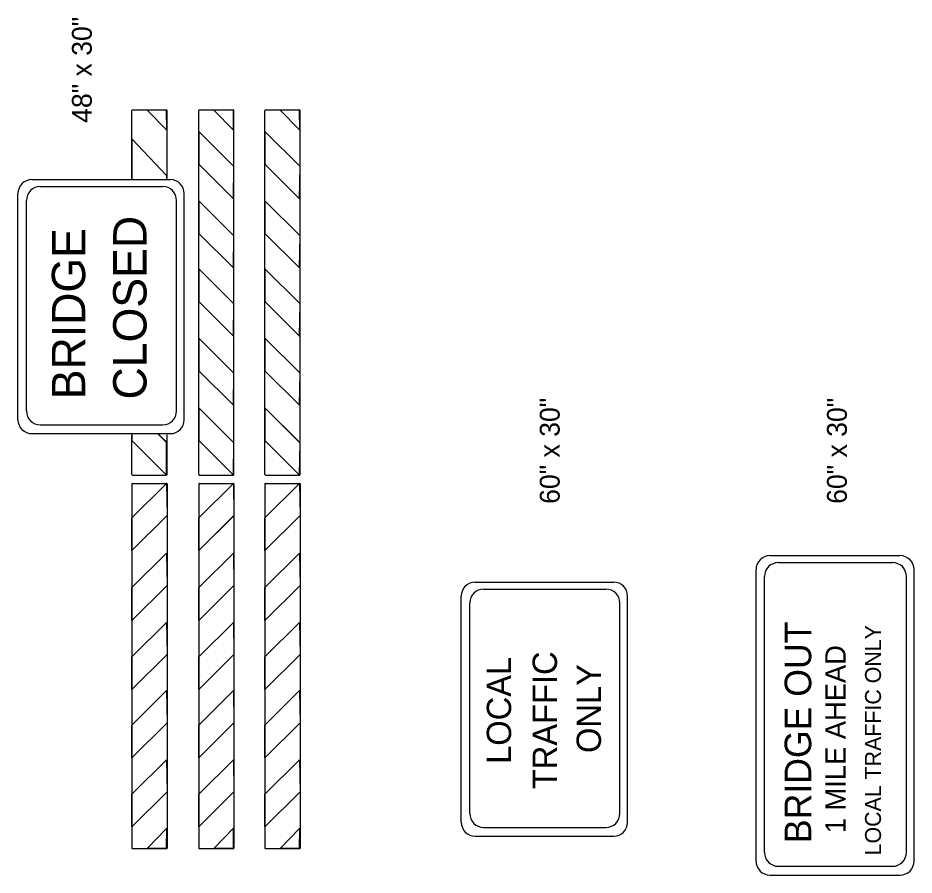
# Model space of a CAD drawing. Extents: x 1123038 to 1172987, y 554419 to 623636.
# Drawn here: x 1155348 to 1160401, y 568298 to 573128 of the extents above; entities that cross this region are included whole.
import ezdxf

# ---------------------------------------------------------------- set-up
doc = ezdxf.new("R2010")
doc.units = 0
doc.layers.add('D_Text_Standard', color=7, linetype='Continuous')
doc.layers.add('Default', color=7, linetype='Continuous')

msp = doc.modelspace()

# ---------------------------------------------------------------- linework, layer by layer
at = {"layer": 'Default'}
for p, q in [((1155991.2, 572223.8), (1155991.2, 572607.5)), ((1155993.8, 572610.1), (1156186.5, 572610.1)), ((1156189.2, 572227.9), (1156189.2, 572607.5)), ((1156367.7, 570555.1), (1156367.7, 572607.5)), ((1156370.3, 572610.1), (1156563.1, 572610.1)), ((1156565.7, 570555.1), (1156565.7, 572607.5)), ((1156741.1, 570555.1), (1156741.1, 572607.5)), ((1156743.7, 572610.1), (1156936.4, 572610.1)), ((1156939, 570555.1), (1156939, 572607.5)), ((1155426.8, 572217.4), (1156207.5, 572217.4)), ((1155348.4, 570864.3), (1155348.4, 572139)), ((1155474.7, 572178.2), (1156164.3, 572178.2)), ((1156285.8, 570864.3), (1156285.8, 572139)), ((1155396.3, 570913.6), (1155396.3, 572099.8)), ((1156242.6, 570913.6), (1156242.6, 572099.8)), ((1156563.1, 570736.7), (1156367.6, 570931)), ((1156936.4, 570736.7), (1156741, 570931)), ((1155474.7, 570835.2), (1156164.3, 570835.2)), ((1155426.8, 570785.9), (1155991.1, 570785.9)), ((1155991.2, 570785.9), (1156207.5, 570785.9)), ((1155991.2, 570555.1), (1155991.2, 570775.6)), ((1156186.5, 570736.7), (1156142.1, 570780.9)), ((1156189.2, 570555.1), (1156189.2, 570779.7)), ((1156186.5, 570552.5), (1155991.1, 570746.9)), ((1156563.1, 570552.5), (1156367.6, 570746.9)), ((1156936.4, 570552.5), (1156741, 570746.9)), ((1155993.8, 570552.5), (1156186.5, 570552.5)), ((1156370.3, 570552.5), (1156563.1, 570552.5)), ((1156743.7, 570552.5), (1156936.4, 570552.5)), ((1156186.7, 570505.6), (1155991.2, 570311.3)), ((1155991.3, 570503), (1155991.3, 568450.6)), ((1155993.9, 570505.6), (1156186.7, 570505.6)), ((1156189.3, 570503), (1156189.3, 568450.6)), ((1156563.2, 570505.6), (1156367.7, 570311.3)), ((1156367.8, 570503), (1156367.8, 568450.6)), ((1156370.4, 570505.6), (1156563.2, 570505.6)), ((1156565.8, 570503), (1156565.8, 568450.6)), ((1156936.5, 570505.6), (1156741.1, 570311.3)), ((1156741.2, 570503), (1156741.2, 568450.6)), ((1156743.8, 570505.6), (1156936.5, 570505.6)), ((1156939.1, 570503), (1156939.1, 568450.6)), ((1156186.7, 570321.5), (1155991.2, 570127.1)), ((1156563.2, 570321.5), (1156367.7, 570127.1)), ((1156936.5, 570321.5), (1156741.1, 570127.1)), ((1159588.6, 570098.5), (1160322.9, 570098.5)), ((1159510.2, 568376.8), (1159510.2, 570020.1)), ((1159636.5, 570059.3), (1160279.7, 570059.3)), ((1160401.3, 568376.8), (1160401.3, 570020.1)), ((1159558.1, 568426.1), (1159558.1, 569981)), ((1160358.1, 568426.1), (1160358.1, 569981)), ((1157926.5, 569949.2), (1158707.1, 569949.2)), ((1157848.1, 568596.2), (1157848.1, 569870.8)), ((1157974.4, 569910.1), (1158663.9, 569910.1)), ((1158785.5, 568596.2), (1158785.5, 569870.8)), ((1157896, 568645.4), (1157896, 569831.7)), ((1158742.3, 568645.4), (1158742.3, 569831.7)), ((1157974.4, 568567.1), (1158663.9, 568567.1)), ((1157926.5, 568517.8), (1158490.8, 568517.8)), ((1158490.8, 568517.8), (1158707.1, 568517.8)), ((1155993.9, 568448), (1156186.7, 568448)), ((1156370.4, 568448), (1156563.2, 568448)), ((1156743.8, 568448), (1156936.5, 568448)), ((1159636.5, 568347.7), (1160279.7, 568347.7)), ((1159588.6, 568298.5), (1160152.9, 568298.5)), ((1160152.9, 568298.5), (1160322.9, 568298.5))]:
    msp.add_line(p, q, dxfattribs=at)
for points in [[(1156187.4, 572495.9), (1156077.2, 572609.5), (1156186.5, 572610.1)], [(1156564, 572495.9), (1156453.7, 572609.5), (1156563.1, 572610.1)], [(1156937.3, 572495.9), (1156827.1, 572609.5), (1156936.4, 572610.1)], [(1156188.9, 572238.3), (1155990, 572447.8), (1155990, 572218.1), (1156187.6, 572218.1)], [(1156563.1, 572109.6), (1156565.7, 572291.4), (1156367.6, 572488.1), (1156367.6, 572303.9)], [(1156936.4, 572109.6), (1156939, 572291.4), (1156741, 572488.1), (1156741, 572303.9)], [(1156563.1, 571719.7), (1156565.7, 571901.5), (1156367.6, 572098.2), (1156367.6, 571914)], [(1156936.4, 571719.7), (1156939, 571901.5), (1156741, 572098.2), (1156741, 571914)], [(1156563.1, 571335.7), (1156565.7, 571517.6), (1156367.6, 571714.3), (1156367.6, 571530.1)], [(1156936.4, 571335.7), (1156939, 571517.6), (1156741, 571714.3), (1156741, 571530.1)], [(1156563.1, 570945.8), (1156565.7, 571127.6), (1156367.6, 571324.4), (1156367.6, 571140.2)], [(1156936.4, 570945.8), (1156939, 571127.6), (1156741, 571324.4), (1156741, 571140.2)], [(1156563.1, 570552.5), (1156565.7, 570734.3), (1156367.6, 570931), (1156367.6, 570746.9)], [(1156936.4, 570552.5), (1156939, 570734.3), (1156741, 570931), (1156741, 570746.9)], [(1156186.7, 570505.6), (1156189.3, 570323.8), (1155991.2, 570127.1), (1155991.2, 570311.3)], [(1156563.2, 570505.6), (1156565.8, 570323.8), (1156367.7, 570127.1), (1156367.7, 570311.3)], [(1156936.5, 570505.6), (1156939.1, 570323.8), (1156741.1, 570127.1), (1156741.1, 570311.3)], [(1156186.7, 570112.3), (1156189.3, 569930.5), (1155991.2, 569733.8), (1155991.2, 569918)], [(1156563.2, 570112.3), (1156565.8, 569930.5), (1156367.7, 569733.8), (1156367.7, 569918)], [(1156936.5, 570112.3), (1156939.1, 569930.5), (1156741.1, 569733.8), (1156741.1, 569918)], [(1156186.7, 569722.4), (1156189.3, 569540.6), (1155991.2, 569343.9), (1155991.2, 569528.1)], [(1156563.2, 569722.4), (1156565.8, 569540.6), (1156367.7, 569343.9), (1156367.7, 569528.1)], [(1156936.5, 569722.4), (1156939.1, 569540.6), (1156741.1, 569343.9), (1156741.1, 569528.1)], [(1156186.7, 569338.5), (1156189.3, 569156.7), (1155991.2, 568959.9), (1155991.2, 569144.1)], [(1156563.2, 569338.5), (1156565.8, 569156.7), (1156367.7, 568959.9), (1156367.7, 569144.1)], [(1156936.5, 569338.5), (1156939.1, 569156.7), (1156741.1, 568959.9), (1156741.1, 569144.1)], [(1156186.7, 568948.6), (1156189.3, 568766.7), (1155991.2, 568570), (1155991.2, 568754.2)], [(1156563.2, 568948.6), (1156565.8, 568766.7), (1156367.7, 568570), (1156367.7, 568754.2)], [(1156936.5, 568948.6), (1156939.1, 568766.7), (1156741.1, 568570), (1156741.1, 568754.2)], [(1156187.6, 568562.2), (1156077.3, 568448.6), (1156186.7, 568448)], [(1156564.1, 568562.2), (1156453.9, 568448.6), (1156563.2, 568448)], [(1156937.4, 568562.2), (1156827.2, 568448.6), (1156936.5, 568448)]]:
    msp.add_lwpolyline(points, close=True, dxfattribs=at)
for points in [[(1156187.4, 572495.9), (1156186.5, 572610.1), (1156077.2, 572609.5), (1156187.4, 572495.9)], [(1156564, 572495.9), (1156563.1, 572610.1), (1156453.7, 572609.5), (1156564, 572495.9)], [(1156937.3, 572495.9), (1156936.4, 572610.1), (1156827.1, 572609.5), (1156937.3, 572495.9)], [(1156188.3, 572228), (1156188.9, 572238.3), (1155990, 572447.8), (1155990, 572218.1), (1156187.6, 572218.1), (1156188.3, 572228)], [(1155991.2, 570785.9), (1155991.1, 570746.9), (1156186.5, 570552.5), (1156189.3, 570735.1), (1156137.1, 570785.3), (1155991.1, 570785.9)], [(1156141.8, 570780.6), (1156137.1, 570785.3), (1155991.1, 570785.9), (1155991.1, 570775.6), (1155991.2, 570775.6), (1155991.2, 570746.9), (1155991.2, 570746.8), (1156186.5, 570552.5), (1156186.5, 570555.1), (1156186.5, 570736.7), (1156141.8, 570780.6)], [(1156187.6, 568562.2), (1156186.7, 568448), (1156077.3, 568448.6), (1156187.6, 568562.2)], [(1156564.1, 568562.2), (1156563.2, 568448), (1156453.9, 568448.6), (1156564.1, 568562.2)], [(1156937.4, 568562.2), (1156936.5, 568448), (1156827.2, 568448.6), (1156937.4, 568562.2)]]:
    msp.add_lwpolyline(points, dxfattribs=at)
for centre, radius, start, end in [((1155993.8, 572607.5), 2.61, 90, 180), ((1156186.5, 572607.5), 2.61, 360, 90), ((1156370.3, 572607.5), 2.61, 90, 180), ((1156563.1, 572607.5), 2.61, 360, 90), ((1156743.7, 572607.5), 2.61, 90, 180), ((1156936.4, 572607.5), 2.61, 360, 90), ((1155426.8, 572139), 78.4, 90, 180), ((1156207.5, 572139), 78.4, 360, 90), ((1155474.7, 572099.8), 78.4, 90, 180), ((1156164.3, 572099.8), 78.4, 360, 90), ((1155474.7, 570913.6), 78.4, 180, 270), ((1156164.3, 570913.6), 78.4, 270, 360), ((1155426.8, 570864.3), 78.4, 180, 270), ((1156207.5, 570864.3), 78.4, 270, 360), ((1155993.8, 570555.1), 2.61, 180, 270), ((1156186.5, 570555.1), 2.61, 270, 360), ((1156370.3, 570555.1), 2.61, 180, 270), ((1156563.1, 570555.1), 2.61, 270, 360), ((1156743.7, 570555.1), 2.61, 180, 270), ((1156936.4, 570555.1), 2.61, 270, 360), ((1155993.9, 570503), 2.61, 90, 180), ((1156186.7, 570503), 2.61, 360, 90), ((1156370.4, 570503), 2.61, 90, 180), ((1156563.2, 570503), 2.61, 360, 90), ((1156743.8, 570503), 2.61, 90, 180), ((1156936.5, 570503), 2.61, 360, 90), ((1159588.6, 570020.1), 78.4, 90, 180), ((1160322.9, 570020.1), 78.4, 360, 90), ((1159636.5, 569981), 78.4, 90, 180), ((1160279.7, 569981), 78.4, 360, 90), ((1157926.5, 569870.8), 78.4, 90, 180), ((1158707.1, 569870.8), 78.4, 360, 90), ((1157974.4, 569831.7), 78.4, 90, 180), ((1158663.9, 569831.7), 78.4, 360, 90), ((1157974.4, 568645.4), 78.4, 180, 270), ((1158663.9, 568645.4), 78.4, 270, 360), ((1157926.5, 568596.2), 78.4, 180, 270), ((1158707.1, 568596.2), 78.4, 270, 360), ((1155993.9, 568450.6), 2.61, 180, 270), ((1156186.7, 568450.6), 2.61, 270, 0), ((1156370.4, 568450.6), 2.61, 180, 270), ((1156563.2, 568450.6), 2.61, 270, 0), ((1156743.8, 568450.6), 2.61, 180, 270), ((1156936.5, 568450.6), 2.61, 270, 0), ((1159636.5, 568426.1), 78.4, 180, 270), ((1160279.7, 568426.1), 78.4, 270, 360), ((1159588.6, 568376.8), 78.4, 180, 270), ((1160322.9, 568376.8), 78.4, 270, 360)]:
    msp.add_arc(centre, radius, start, end, dxfattribs=at)

# ---------------------------------------------------------------- texts
at = {"layer": 'D_Text_Standard'}
for s, p in [('48" x 30"', (1155765, 572537.3)), ('60" x 30"', (1158403, 570390.3)), ('60" x 30"', (1160022.2, 570390.3))]:
    msp.add_text(s, height=111.99, rotation=90, dxfattribs=at).set_placement(p)
at = {"layer": 'Default'}
for s, height, p in [('CLOSED', 188.1, (1156073.5, 570978.6)), ('BRIDGE', 188.1, (1155727.9, 570979.7)), ('BRIDGE OUT', 150, (1159821.5, 568478.5)), ('LOCAL TRAFFIC ONLY', 90, (1160214.7, 568409.5)), ('1 MILE AHEAD', 115, (1160015.6, 568534.4)), ('LOCAL', 137.5, (1158129.4, 568925)), ('TRAFFIC', 137.5, (1158387.9, 568782.6)), ('ONLY', 137.5, (1158635.8, 568986.4))]:
    msp.add_text(s, height=height, rotation=90, dxfattribs=at).set_placement(p)

doc.saveas('drawing.dxf')
